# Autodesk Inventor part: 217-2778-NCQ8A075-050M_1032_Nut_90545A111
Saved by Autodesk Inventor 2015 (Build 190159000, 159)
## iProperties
Created: 2014-11
Part Number: 217-2778-NCQ8A075-050M_1032_Nut_90545A111
Material: Generic
Document SubType Name: Modeling
Designer: User
Density: 1 g/cm^3
Appearance: Default
Author: User
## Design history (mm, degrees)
node "217-2778-NCQ8A075-050M_1032_Nut_90545A111.ipt1"
node "Cut-Extrude9"
node "Base1"
